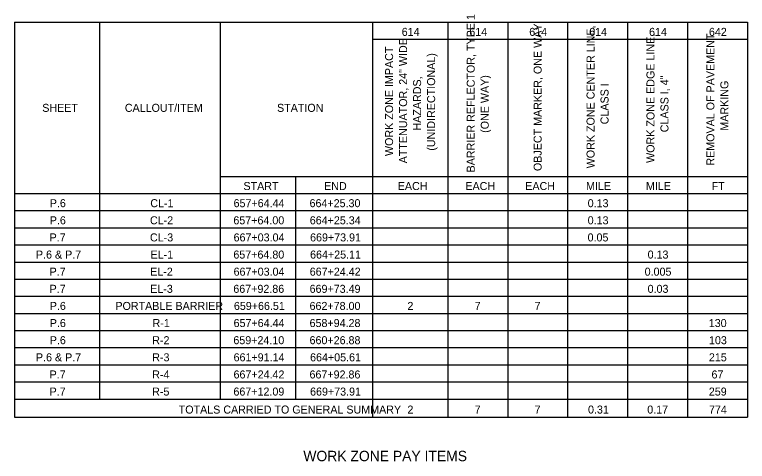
# Model space of a CAD drawing. Extents: x 0 to 51.6, y 0 to 43.5.
# Drawn here: x 37.53 to 51.62, y 11.64 to 20.24 of the extents above; entities that cross this region are included whole.
import ezdxf

# ---------------------------------------------------------------- set-up
doc = ezdxf.new("R2010")
doc.units = 0
doc.layers.add('SH_Text', color=7, linetype='Continuous')

msp = doc.modelspace()

# ---------------------------------------------------------------- linework, layer by layer
at = {"layer": 'SH_Text'}
for p, q in [((37.525, 20.09), (51.624, 20.09)), ((37.525, 20.09), (37.525, 12.497)), ((39.156, 20.09), (39.156, 12.843)), ((41.478, 20.09), (41.478, 12.843)), ((44.41, 20.09), (44.41, 12.497)), ((45.859, 20.09), (45.859, 12.497)), ((47.012, 20.09), (47.012, 12.497)), ((48.165, 20.09), (48.165, 12.497)), ((49.318, 20.09), (49.318, 12.497)), ((50.471, 20.09), (50.471, 12.497)), ((51.624, 20.09), (51.624, 12.497)), ((44.41, 19.761), (51.624, 19.761)), ((41.478, 17.125), (51.624, 17.125)), ((42.928, 17.125), (42.928, 12.843)), ((37.525, 16.796), (51.624, 16.796)), ((37.525, 16.467), (51.624, 16.467)), ((37.525, 16.137), (51.624, 16.137)), ((37.525, 15.808), (51.624, 15.808)), ((37.525, 15.478), (51.624, 15.478)), ((37.525, 15.149), (51.624, 15.149)), ((37.525, 14.819), (51.624, 14.819)), ((37.525, 14.49), (51.624, 14.49)), ((37.525, 14.161), (51.624, 14.161)), ((37.525, 13.831), (51.624, 13.831)), ((37.525, 13.502), (51.624, 13.502)), ((37.525, 13.172), (51.624, 13.172)), ((37.525, 12.843), (51.624, 12.843)), ((37.525, 12.497), (51.624, 12.497))]:
    msp.add_line(p, q, dxfattribs=at)

# ---------------------------------------------------------------- texts
for s, p in [('BARRIER REFLECTOR, TYPE 1 ', (46.378, 17.201)), ('OBJECT MARKER, ONE WAY', (47.666, 17.227)), ('WORK ZONE CENTER LINE, ', (48.684, 17.28)), ('ATTENUATOR, 24" WIDE ', (45.077, 17.376)), ('WORK ZONE EDGE LINE, ', (49.837, 17.384)), ('REMOVAL OF PAVEMENT ', (50.99, 17.332)), ('WORK ZONE IMPACT ', (44.807, 17.516)), ('(UNIDIRECTIONAL)', (45.616, 17.619)), ('(ONE WAY)', (46.648, 17.962)), ('CLASS I, 4"', (50.106, 17.973)), ('HAZARDS, ', (45.346, 18.006)), ('CLASS I', (48.953, 18.126)), ('MARKING', (51.259, 18.004))]:
    msp.add_text(s, height=0.154, rotation=90, dxfattribs=at).set_placement(p)
for s, height, p in [('614', 0.154, (44.973, 19.827)), ('614', 0.154, (46.274, 19.827)), ('614', 0.154, (47.427, 19.827)), ('614', 0.154, (48.58, 19.827)), ('614', 0.154, (49.733, 19.827)), ('642', 0.154, (50.885, 19.827)), ('SHEET', 0.154, (38.056, 18.366)), ('CALLOUT/ITEM', 0.154, (39.645, 18.366)), ('STATION', 0.154, (42.574, 18.366)), ('START', 0.154, (41.928, 16.862)), ('END', 0.154, (43.48, 16.862)), ('EACH', 0.154, (44.897, 16.862)), ('EACH', 0.154, (46.198, 16.862)), ('EACH', 0.154, (47.351, 16.862)), ('MILE', 0.154, (48.52, 16.862)), ('MILE', 0.154, (49.673, 16.862)), ('FT', 0.154, (50.937, 16.862)), ('P.6', 0.154, (38.201, 16.532)), ('CL-1', 0.154, (40.135, 16.532)), ('657+64.44', 0.154, (41.738, 16.532)), ('664+25.30', 0.154, (43.2, 16.532)), ('0.13', 0.154, (48.552, 16.532)), ('P.6', 0.154, (38.201, 16.203)), ('CL-2', 0.154, (40.129, 16.203)), ('657+64.00', 0.154, (41.734, 16.203)), ('664+25.34', 0.154, (43.204, 16.203)), ('0.13', 0.154, (48.552, 16.203)), ('P.7', 0.154, (38.198, 15.874)), ('CL-3', 0.154, (40.129, 15.874)), ('667+03.04', 0.154, (41.738, 15.874)), ('669+73.91', 0.154, (43.21, 15.874)), ('0.05', 0.154, (48.55, 15.874)), ('P.6 & P.7', 0.154, (37.935, 15.544)), ('EL-1', 0.154, (40.139, 15.544)), ('657+64.80', 0.154, (41.734, 15.544)), ('664+25.11', 0.154, (43.21, 15.544)), ('0.13', 0.154, (49.705, 15.544)), ('P.7', 0.154, (38.198, 15.215)), ('EL-2', 0.154, (40.133, 15.215)), ('667+03.04', 0.154, (41.738, 15.215)), ('667+24.42', 0.154, (43.203, 15.215)), ('0.005', 0.154, (49.648, 15.215)), ('P.7', 0.154, (38.198, 14.885)), ('EL-3', 0.154, (40.133, 14.885)), ('667+92.86', 0.154, (41.733, 14.885)), ('669+73.49', 0.154, (43.201, 14.885)), ('0.03', 0.154, (49.705, 14.885)), ('P.6', 0.154, (38.201, 14.556)), ('PORTABLE BARRIER', 0.154, (39.464, 14.556)), ('659+66.51', 0.154, (41.744, 14.556)), ('662+78.00', 0.154, (43.2, 14.556)), ('2', 0.154, (45.083, 14.556)), ('7', 0.154, (46.377, 14.556)), ('7', 0.154, (47.53, 14.556)), ('P.6', 0.154, (38.201, 14.227)), ('657+64.44', 0.154, (41.738, 14.227)), ('658+94.28', 0.154, (43.2, 14.227)), ('130', 0.154, (50.882, 14.227)), ('R-1', 0.154, (40.179, 14.227)), ('P.6', 0.154, (38.201, 13.897)), ('R-2', 0.154, (40.173, 13.897)), ('659+24.10', 0.154, (41.734, 13.897)), ('660+26.88', 0.154, (43.2, 13.897)), ('103', 0.154, (50.886, 13.897)), ('P.6 & P.7', 0.154, (37.935, 13.568)), ('R-3', 0.154, (40.173, 13.568)), ('661+91.14', 0.154, (41.738, 13.568)), ('664+05.61', 0.154, (43.21, 13.568)), ('215', 0.154, (50.884, 13.568)), ('667+24.42', 0.154, (41.737, 13.238)), ('667+92.86', 0.154, (43.199, 13.238)), ('67', 0.154, (50.934, 13.238)), ('P.7', 0.154, (38.198, 13.238)), ('R-4', 0.154, (40.173, 13.238)), ('P.7', 0.154, (38.198, 12.909)), ('R-5', 0.154, (40.171, 12.909)), ('667+12.09', 0.154, (41.735, 12.909)), ('669+73.91', 0.154, (43.21, 12.909)), ('259', 0.154, (50.883, 12.909)), ('TOTALS CARRIED TO GENERAL SUMMARY', 0.154, (40.682, 12.563)), ('2', 0.154, (45.083, 12.563)), ('7', 0.154, (46.377, 12.563)), ('7', 0.154, (47.53, 12.563)), ('0.31', 0.154, (48.558, 12.563)), ('0.17', 0.154, (49.698, 12.563)), ('774', 0.154, (50.886, 12.563)), ('WORK ZONE PAY ITEMS', 0.2, (43.08, 11.647))]:
    msp.add_text(s, height=height, dxfattribs=at).set_placement(p)

doc.saveas('drawing.dxf')
